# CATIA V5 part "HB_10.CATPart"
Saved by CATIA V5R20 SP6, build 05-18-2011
Part number: HB_10
Bounding box of the stored display mesh (mm): x -79 to 0, y 0 to 790, z 0 to 113.2
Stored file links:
  E:\#01 CATIA Lecture Materials\#06 DMU\#11 DMU Page01 KIN EX11\HB_10.CATPart
  E:\공학과제\HB-16.CATPart
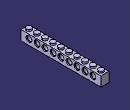
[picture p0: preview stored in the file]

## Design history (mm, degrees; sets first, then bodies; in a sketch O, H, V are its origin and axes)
Body1 (main body)
  Sketch1 on xy-plane, origin (0, 0, 0), H (1, 0, 0), V (0, 1, 0)
    circle A1 centre (-39.5, 39.5) radius 24.5
    point P1 (-39.5, 39.5)
    reference projected line E1 (0, 0) -> (0, 1264)
    reference projected line E2 (-79, 0) -> (-79, 1264)
    reference projected line E3 (-79, 0) -> (0, 0)
    radius A1 = 24.5
    distance P1 E3 = 39.5
    equidistance: E1 E2 P1
  Pad1: profile Sketch1, direction (0, 0, 1), length 113.2
  RectPattern1: of the body so far, direction 1 instances 10, spacing 79, along yz-plane
  Sketch2 on zx-plane, origin (0, 0, 0), H (-1, 0, 0), V (0, 0, 1)
    point P1 (0, 96)
    line L1 (0, 96) -> (79, 96)
    line L2 (79, 96) -> (79, 0)
    line L3 (79, 0) -> (0, 0)
    line L4 (0, 0) -> (0, 96)
    point P3 (79, 0)
    distance L2 L4 = 79
    length L2 = 96
    coincidence: P1 V, P3 H
    horizontal: L1 H, L3 H
    vertical: L2 V, L4 V
  Pad2: profile Sketch2, direction (0, 1, 0), length 790 {= RectPattern1.Nb1 * (79*1mm)}
  Plane1: type Offset, RefPlane zx-plane, Offset 79
  Sketch3 on Plane1, origin (0, 79, 0), H (-1, 0, 0), V (0, 0, 1)
    axis line L1 (95.3003, 56) -> (-23.8651, 56)
    reference projected line E1 (79, 96) -> (0, 96) from edge [start face of Pad2 | face of Pad2 from Sketch2.L1]
    point P3 (79, 56)
    line L2 (79, 56) -> (79, 85.25)
    line L3 (79, 85.25) -> (69, 85.25)
    line L4 (69, 85.25) -> (69, 80.25)
    line L5 (69, 80.25) -> (10, 80.25)
    line L6 (10, 80.25) -> (10, 85.25)
    point P8 (10, 85.25)
    line L7 (10, 85.25) -> (0, 85.25)
    point P9 (0, 85.25)
    line L8 (0, 85.25) -> (0, 56)
    point P10 (0, 56)
    reference projected line E2 (79, 0) -> (79, 96) from edge [start face of Pad2 | face of Pad2 from Sketch2.L2]
    distance L1 E1 = 40
    distance L8 L6 = 10
    distance L4 L2 = 10
    distance L5 L1 = 24.25
    distance L7 L1 = 29.25
    horizontal: L1 H, L3 H, L5 H, L7 H
    coincidence: P3 L1, P8 L3, P9 V, P10 L1, L2 E2
    vertical: L2 V, L4 V, L6 V, L8 V
  Groove1: profile Sketch3, axis Sketch3.L1, angle 360
  RectPattern2: of Groove1, direction 1 instances 9 {= RectPattern1.Nb1 - 1}, spacing 79, along edge [face of Pad2 from Sketch2.L4 | face of Pad2 from Sketch2.L1]
  Shell1: ExtOffset 0, Face face of Pad2, IntOffset 10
